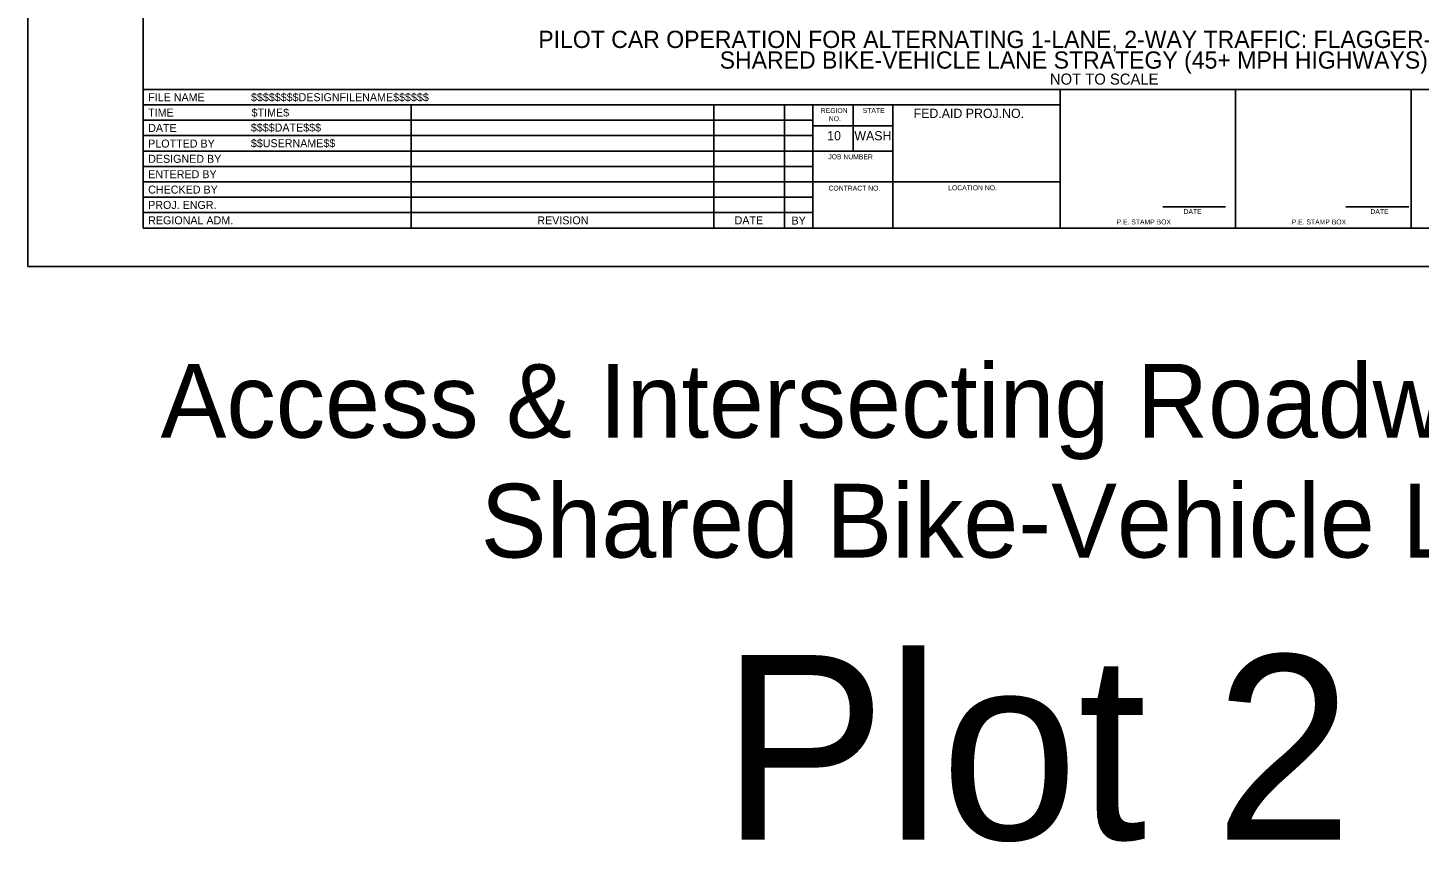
# Model space of a CAD drawing. Extents: x 99999.1 to 100095.7, y 99995 to 100010.7.
# Drawn here: x 100019.06 to 100030.38, y 99995.01 to 100001.63 of the extents above; entities that cross this region are included whole.
import ezdxf

# ---------------------------------------------------------------- set-up
doc = ezdxf.new("R2010")
doc.units = 0
for name, color, linetype in [('SH_DE_DetailHeading1Text', 7, 'Continuous'), ('SH_GI_PlotLimits', 7, 'Continuous'), ('SH_GI_SheetBorder', 7, 'Continuous'), ('SH_GI_SheetLocationText', 7, 'Continuous'), ('SH_GI_SheetTextInCells', 7, 'Continuous'), ('SH_GI_TitleBlockText', 7, 'Continuous')]:
    doc.layers.add(name, color=color, linetype=linetype)

msp = doc.modelspace()

# ---------------------------------------------------------------- linework, layer by layer
at = {"layer": 'SH_GI_PlotLimits'}
msp.add_lwpolyline([(100019.062, 99999.687), (100036.062, 99999.687), (100036.062, 100010.687), (100019.062, 100010.687)], close=True, dxfattribs=at)
at = {"layer": 'SH_GI_SheetBorder'}
for p, q in [((100020, 100010.375), (100020, 100000)), ((100020, 100001.126), (100035.75, 100001.126)), ((100027.457, 100000), (100027.457, 100001.126)), ((100028.883, 100000), (100028.883, 100001.126)), ((100030.309, 100001.126), (100030.309, 100000)), ((100020, 100001.001), (100027.457, 100001.001)), ((100022.179, 100001.001), (100022.179, 100000)), ((100024.641, 100001.001), (100024.641, 100000)), ((100025.216, 100001.001), (100025.216, 100000)), ((100025.445, 100001.001), (100025.445, 100000)), ((100025.772, 100000.625), (100025.772, 100001.001)), ((100026.096, 100000), (100026.096, 100001.001)), ((100020, 100000.876), (100022.182, 100000.876)), ((100022.182, 100000.876), (100025.447, 100000.876)), ((100026.096, 100000.831), (100025.447, 100000.831)), ((100020, 100000.751), (100022.182, 100000.751)), ((100022.182, 100000.751), (100025.447, 100000.751)), ((100020, 100000.625), (100025.447, 100000.625)), ((100026.096, 100000.625), (100025.447, 100000.625)), ((100020, 100000.5), (100025.447, 100000.5)), ((100020, 100000.375), (100025.447, 100000.375)), ((100027.457, 100000.375), (100025.447, 100000.375)), ((100020, 100000.25), (100025.447, 100000.25)), ((100020, 100000.125), (100025.447, 100000.125)), ((100028.29, 100000.173), (100028.802, 100000.173)), ((100029.78, 100000.173), (100030.291, 100000.173)), ((100020, 100000), (100035.75, 100000))]:
    msp.add_line(p, q, dxfattribs=at)

# ---------------------------------------------------------------- texts
at = {"layer": 'SH_DE_DetailHeading1Text'}
for s, height, p in [('PILOT CAR OPERATION FOR ALTERNATING 1-LANE, 2-WAY TRAFFIC: FLAGGER-CONTROLLED', 0.14, (100023.213, 100001.464)), ('SHARED BIKE-VEHICLE LANE STRATEGY (45+ MPH HIGHWAYS)', 0.14, (100024.688, 100001.296)), ('NOT TO SCALE', 0.09, (100027.373, 100001.166))]:
    msp.add_text(s, height=height, rotation=360, dxfattribs=at).set_placement(p)
at = {"layer": 'SH_GI_SheetLocationText'}
for s, height, p in [('Access & Intersecting Roadway Details', 0.6, (100020.142, 99998.295)), ('Shared Bike-Vehicle Lane', 0.6, (100022.745, 99997.32)), ('Plot 2', 1.5, (100024.702, 99995.027))]:
    msp.add_text(s, height=height, dxfattribs=at).set_placement(p)
at = {"layer": 'SH_GI_SheetTextInCells'}
for s, height, p in [('FILE NAME', 0.0651, (100020.041, 100001.031)), ('TIME', 0.0651, (100020.041, 100000.906)), ('REGION', 0.04, (100025.51, 100000.935)), ('NO.', 0.04, (100025.575, 100000.869)), ('STATE', 0.04, (100025.851, 100000.936)), ('FED.AID PROJ.NO.', 0.07506, (100026.265, 100000.895)), ('DATE', 0.0651, (100020.041, 100000.781)), ('10', 0.0751, (100025.562, 100000.713)), ('WASH', 0.0751, (100025.783, 100000.713)), ('PLOTTED BY', 0.0651, (100020.041, 100000.654)), ('DESIGNED BY', 0.06505, (100020.041, 100000.53)), ('JOB NUMBER', 0.04, (100025.571, 100000.559)), ('ENTERED BY', 0.0651, (100020.041, 100000.405)), ('CHECKED BY', 0.0651, (100020.041, 100000.28)), ('CONTRACT NO.', 0.04003, (100025.573, 100000.304)), ('LOCATION NO.', 0.04003, (100026.546, 100000.307)), ('PROJ. ENGR.', 0.06505, (100020.041, 100000.155)), ('REGIONAL ADM.', 0.06505, (100020.041, 100000.03)), ('REVISION', 0.0651, (100023.205, 100000.03)), ('DATE', 0.04, (100028.46, 100000.114)), ('DATE', 0.04, (100029.979, 100000.114)), ('DATE', 0.0651, (100024.809, 100000.03)), ('BY', 0.0651, (100025.272, 100000.028)), ('P.E. STAMP BOX', 0.04003, (100027.915, 100000.029)), ('P.E. STAMP BOX', 0.04003, (100029.339, 100000.029))]:
    msp.add_text(s, height=height, dxfattribs=at).set_placement(p)
at = {"layer": 'SH_GI_TitleBlockText'}
for s, height, p in [('$$$$$$$$DESIGNFILENAME$$$$$$', 0.06505, (100020.877, 100001.031)), ('$TIME$', 0.0651, (100020.882, 100000.906)), ('$$$$DATE$$$', 0.06505, (100020.876, 100000.784)), ('$$USERNAME$$', 0.06505, (100020.876, 100000.657))]:
    msp.add_text(s, height=height, dxfattribs=at).set_placement(p)

doc.saveas('drawing.dxf')
